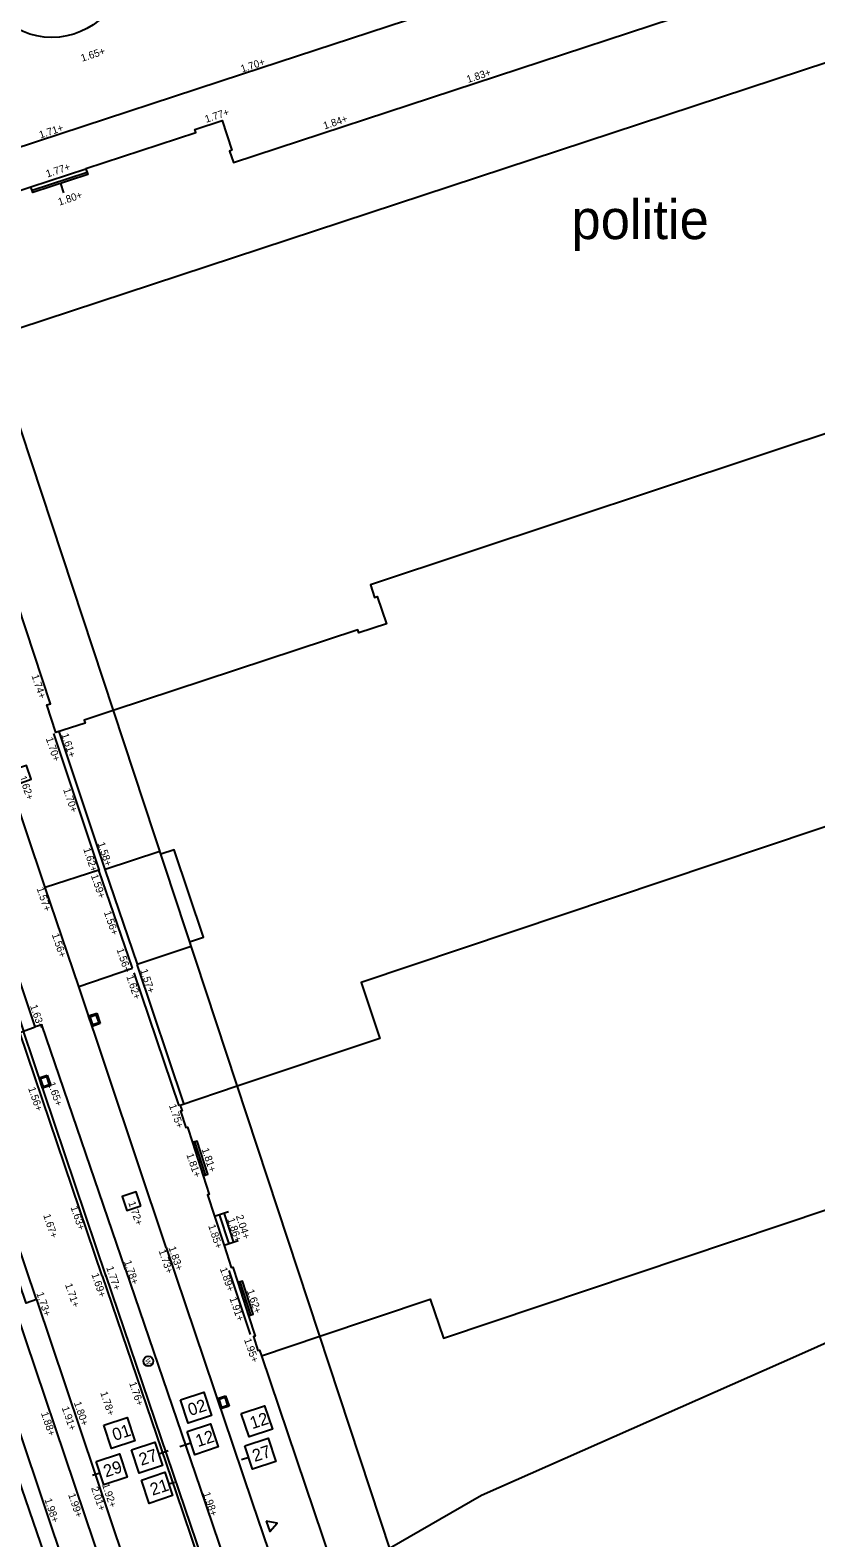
# Model space of a CAD drawing. Extents: x 122462 to 123306, y 485548 to 486417.
# Drawn here: x 122832.1 to 122864.1, y 486111.7 to 486173.1 of the extents above; entities that cross this region are included whole.
import ezdxf

# ---------------------------------------------------------------- set-up
doc = ezdxf.new("R2010")
doc.units = 0
for name, color, linetype in [('B nummers', 7, 'Continuous'), ('B-WE-AL-WERKGRENS-G', 7, 'Continuous'), ('B-WE-GR-BOOM-S', 7, 'Continuous'), ('B-WE-IE-MEUBILAIR_WEGMEUBILAIR-S', 7, 'Continuous'), ('B-WE-IE-TERREINAFSCHEIDING_KUNSTMATIG_HEKWERK-G', 7, 'Continuous'), ('B-WE-OG-BEBOUWING_RAAM-G', 7, 'Continuous'), ('B-WE-OG-BEBOUWING_TRAP-G', 7, 'Continuous'), ('B-WE-OG-HOOGTEPUNT-S', 7, 'Continuous'), ('B-WE-OG-TOPOGRAFIE_GEVELDETAIL-G', 7, 'Continuous'), ('B-WE-OG-TOPOGRAFIE_MUUR-G', 7, 'Continuous'), ('B-WE-OG-TOPOKAART-G', 7, 'Continuous'), ('B-WE-VH-KANTOPSLUITING_OPSLUITBAND_100X200-G', 7, 'Continuous'), ('B-WE-VH-MATERIAALGRENS-G', 7, 'Continuous'), ('B-WE-VW-MARKERING_LANGS_STREEP_DOORGETROKKEN_010-G', 7, 'Continuous'), ('Level 1', 7, 'Continuous'), ('Level 16', 7, 'Continuous'), ('Level 17', 7, 'Continuous'), ('Level 62', 7, 'Continuous'), ('V Inritband 100x50', 7, 'Continuous'), ('V materiaalscheiding algemeen', 7, 'Continuous'), ('V meubilair trammast', 7, 'Continuous'), ('V Rails', 7, 'Continuous'), ('V riool putdeksel', 7, 'Continuous'), ('V riool trottoirkolk', 7, 'Continuous'), ('V RWS-band 115-225x250 mm specie', 7, 'Continuous'), ('V trottoirband 180-200x250 mm specie', 7, 'Continuous')]:
    doc.layers.add(name, color=color, linetype=linetype)

msp = doc.modelspace()

# ---------------------------------------------------------------- linework, layer by layer
at = {"layer": 'B nummers'}
for p, q in [((122837.339, 486115.174), (122837.732, 486115.304)), ((122838.65, 486115.607), (122838.202, 486115.459)), ((122841.002, 486115.014), (122840.712, 486114.918)), ((122834.948, 486114.385), (122834.645, 486114.286)), ((122837.746, 486113.94), (122837.984, 486114.018))]:
    msp.add_line(p, q, dxfattribs=at)
for points in [[(122838.226, 486117.362), (122839.176, 486117.676), (122839.489, 486116.726), (122838.539, 486116.413)], [(122840.701, 486116.81), (122841.651, 486117.124), (122841.964, 486116.174), (122841.015, 486115.861)], [(122835.102, 486116.332), (122836.052, 486116.645), (122836.365, 486115.695), (122835.415, 486115.382)], [(122838.494, 486116.082), (122839.443, 486116.395), (122839.757, 486115.446), (122838.807, 486115.132)], [(122836.232, 486115.336), (122837.182, 486115.649), (122837.495, 486114.699), (122836.546, 486114.386)], [(122840.846, 486115.489), (122841.795, 486115.802), (122842.109, 486114.853), (122841.159, 486114.539)], [(122834.791, 486114.86), (122835.741, 486115.174), (122836.054, 486114.224), (122835.105, 486113.911)], [(122836.64, 486114.101), (122837.589, 486114.415), (122837.903, 486113.465), (122836.953, 486113.152)]]:
    msp.add_lwpolyline(points, close=True, dxfattribs=at)
at = {"layer": 'B-WE-AL-WERKGRENS-G'}
msp.add_lwpolyline([(122857.632, 486078.279), (122830.484, 486160.606), (122900.937, 486183.81), (122887.855, 486222.555), (122665.445, 486149.273), (122678.196, 486110.449), (122807.072, 486152.895), (122835.324, 486068.154)], dxfattribs=at)
at = {"layer": 'B-WE-GR-BOOM-S'}
msp.add_circle((122832.992, 486175.817), 3, dxfattribs=at)
at = {"layer": 'B-WE-IE-MEUBILAIR_WEGMEUBILAIR-S'}
msp.add_circle((122836.917, 486118.938), 0.2, dxfattribs=at)
at = {"layer": 'B-WE-IE-TERREINAFSCHEIDING_KUNSTMATIG_HEKWERK-G'}
for points in [[(122837.383, 486139.685), (122835.162, 486138.946), (122833.293, 486144.564)], [(122838.657, 486135.821), (122836.47, 486135.09)], [(122838.376, 486129.388), (122836.47, 486135.09)]]:
    msp.add_lwpolyline(points, dxfattribs=at)
at = {"layer": 'B-WE-OG-BEBOUWING_RAAM-G'}
for points in [[(122838.71, 486127.837), (122839.147, 486126.487), (122839.338, 486126.549), (122838.901, 486127.898)], [(122840.555, 486122.138), (122840.992, 486120.788), (122841.182, 486120.85), (122840.745, 486122.199)]]:
    msp.add_lwpolyline(points, close=True, dxfattribs=at)
for points in [[(122839.242, 486126.518), (122838.805, 486127.868)], [(122841.087, 486120.819), (122840.65, 486122.169)]]:
    msp.add_lwpolyline(points, dxfattribs=at)
at = {"layer": 'B-WE-OG-BEBOUWING_TRAP-G'}
for p, q in [((122839.61, 486124.846), (122839.998, 486123.648)), ((122839.8, 486124.908), (122840.188, 486123.71)), ((122839.99, 486124.97), (122840.378, 486123.771))]:
    msp.add_line(p, q, dxfattribs=at)
at = {"layer": 'B-WE-OG-TOPOGRAFIE_GEVELDETAIL-G'}
for p, q in [((122832.19, 486166.597), (122834.429, 486167.331)), ((122833.341, 486166.869), (122833.465, 486166.489))]:
    msp.add_line(p, q, dxfattribs=at)
msp.add_lwpolyline([(122832.144, 486166.739), (122834.382, 486167.474), (122834.46, 486167.236), (122832.222, 486166.501)], close=True, dxfattribs=at)
at = {"layer": 'B-WE-OG-TOPOGRAFIE_MUUR-G'}
msp.add_line((122841.519, 486119.16), (122844.35, 486110.759), dxfattribs=at)
at = {"layer": 'B-WE-OG-TOPOKAART-G'}
for points in [[(122834.381, 486167.476), (122838.846, 486168.947), (122838.807, 486169.064), (122839.92, 486169.429), (122840.318, 486168.223), (122840.226, 486168.193), (122840.381, 486167.723), (122860.049, 486174.179)], [(122835.493, 486145.416), (122834.311, 486145.025), (122834.351, 486144.904), (122833.159, 486144.52), (122832.786, 486145.648), (122832.936, 486145.697), (122826.954, 486163.84), (122826.803, 486163.791), (122826.41, 486164.979), (122827.587, 486165.368), (122827.626, 486165.251), (122832.144, 486166.739)], [(122840.535, 486130.128), (122838.219, 486129.35), (122838.292, 486129.132), (122838.229, 486129.11), (122838.446, 486128.445), (122838.507, 486128.465), (122838.71, 486127.837)], [(122839.147, 486126.487), (122839.393, 486125.728), (122839.331, 486125.708), (122839.61, 486124.846), (122840.181, 486125.031)], [(122840.569, 486123.833), (122839.998, 486123.648), (122840.29, 486122.746), (122840.352, 486122.766), (122840.555, 486122.138)], [(122840.992, 486120.788), (122841.26, 486119.959), (122841.198, 486119.939), (122841.38, 486119.37), (122841.443, 486119.391), (122841.519, 486119.16), (122843.889, 486119.956)]]:
    msp.add_lwpolyline(points, dxfattribs=at)
at = {"layer": 'B-WE-VH-KANTOPSLUITING_OPSLUITBAND_100X200-G'}
for points in [[(122834.927, 486138.912), (122833.07, 486144.482)], [(122838.167, 486129.333), (122836.336, 486134.745)], [(122841.076, 486120.024), (122840.202, 486122.634)]]:
    msp.add_lwpolyline(points, dxfattribs=at)
at = {"layer": 'B-WE-VH-MATERIAALGRENS-G'}
for points in [[(122826.354, 486164.961), (122825.848, 486166.443), (122832.41, 486168.591), (122840.754, 486171.332), (122848.12, 486173.75), (122858.853, 486177.307), (122858.545, 486178.241), (122874.617, 486183.538), (122874.928, 486182.584), (122877.008, 486183.297), (122898.435, 486190.341)], [(122836.271, 486134.939), (122834.911, 486138.929)], [(122836.476, 486135.092), (122835.162, 486138.946)]]:
    msp.add_lwpolyline(points, dxfattribs=at)
at = {"layer": 'B-WE-VW-MARKERING_LANGS_STREEP_DOORGETROKKEN_010-G'}
msp.add_lwpolyline([(122842.379, 486082.508), (122834.669, 486105.323), (122830.244, 486118.192), (122825.281, 486132.973), (122822.384, 486141.602), (122818.71, 486152.508)], dxfattribs=at)
at = {"layer": 'Level 1'}
for points in [[(122909.585, 486143.395), (122901.057, 486168.787), (122881.468, 486162.304), (122881.638, 486161.79), (122881.732, 486161.821), (122882.121, 486160.646), (122880.986, 486160.273), (122880.955, 486160.368), (122867.199, 486155.844), (122867.231, 486155.749), (122866.093, 486155.375), (122865.709, 486156.53), (122865.804, 486156.562), (122865.635, 486157.072), (122845.954, 486150.537), (122846.124, 486150.024), (122846.234, 486150.06), (122846.601, 486148.954), (122845.482, 486148.584), (122845.442, 486148.705), (122835.493, 486145.416)], [(122899.919, 486149.707), (122899.047, 486152.304), (122845.573, 486134.345), (122846.335, 486132.076), (122840.535, 486130.128)], [(122843.889, 486119.956), (122848.39, 486121.468), (122848.927, 486119.869), (122903.756, 486138.283), (122903.184, 486139.984)]]:
    msp.add_lwpolyline(points, dxfattribs=at)
at = {"layer": 'Level 16'}
msp.add_lwpolyline([(122846.733, 486111.33), (122850.475, 486113.488), (122863.386, 486119.194), (122871.86, 486122.983), (122876.67, 486124.799)], dxfattribs=at)
at = {"layer": 'Level 17'}
msp.add_lwpolyline([(122838.595, 486136.01), (122839.16, 486136.199), (122837.973, 486139.753), (122837.421, 486139.569)], dxfattribs=at)
at = {"layer": 'V Inritband 100x50'}
for points in [[(122832.367, 486121.446), (122831.947, 486121.305), (122828.09, 486132.668), (122825.079, 486141.609), (122824.762, 486142.578), (122825.19, 486142.715)], [(122832.367, 486121.446), (122828.514, 486132.846), (122825.512, 486141.812), (122825.19, 486142.715)], [(122831.838, 486132.366), (122832.314, 486132.542), (122829.781, 486140.105), (122829.312, 486139.948), (122831.838, 486132.366)]]:
    msp.add_lwpolyline(points, dxfattribs=at)
at = {"layer": 'V materiaalscheiding algemeen'}
for points in [[(122834.088, 486134.186), (122832.725, 486138.213)], [(122835.041, 486122.41), (122831.696, 486132.317), (122831.838, 486132.366)], [(122835.992, 486122.672), (122832.591, 486132.63), (122832.314, 486132.542)], [(122835.041, 486122.41), (122838.047, 486113.577), (122840.172, 486107.322), (122840.315, 486107.372)], [(122835.992, 486122.672), (122839.022, 486113.767)]]:
    msp.add_lwpolyline(points, dxfattribs=at)
at = {"layer": 'V meubilair trammast'}
msp.add_lwpolyline([(122841.718, 486112.431), (122841.863, 486112.005), (122842.159, 486112.343)], close=True, dxfattribs=at)
at = {"layer": 'V Rails'}
for p, q in [((122818.309, 486155.586), (122834.974, 486106.268)), ((122819.673, 486156.047), (122836.339, 486106.728))]:
    msp.add_line(p, q, dxfattribs=at)
at = {"layer": 'V riool putdeksel'}
for points in [[(122831.39, 486142.988), (122831.59, 486142.422), (122832.156, 486142.622), (122831.956, 486143.188)], [(122836.618, 486125.262), (122836.428, 486125.832), (122835.858, 486125.642), (122836.048, 486125.072)]]:
    msp.add_lwpolyline(points, close=True, dxfattribs=at)
at = {"layer": 'V riool trottoirkolk'}
for p, q in [((122834.488, 486132.992), (122834.82, 486133.103)), ((122834.631, 486132.565), (122834.488, 486132.992)), ((122834.504, 486132.944), (122834.509, 486132.946)), ((122834.547, 486132.864), (122834.521, 486132.939)), ((122834.536, 486132.849), (122834.54, 486132.851)), ((122834.544, 486132.826), (122834.548, 486132.827)), ((122834.586, 486132.745), (122834.561, 486132.821)), ((122834.82, 486133.103), (122834.963, 486132.676)), ((122834.575, 486132.731), (122834.58, 486132.732)), ((122834.583, 486132.707), (122834.588, 486132.709)), ((122834.611, 486132.671), (122834.601, 486132.702)), ((122834.626, 486132.626), (122834.611, 486132.671)), ((122834.615, 486132.612), (122834.62, 486132.614)), ((122834.963, 486132.676), (122834.631, 486132.565)), ((122832.475, 486130.474), (122832.807, 486130.586)), ((122832.619, 486130.048), (122832.475, 486130.474)), ((122832.491, 486130.427), (122832.496, 486130.428)), ((122832.534, 486130.346), (122832.508, 486130.422)), ((122832.807, 486130.586), (122832.95, 486130.159)), ((122832.523, 486130.332), (122832.528, 486130.334)), ((122832.531, 486130.308), (122832.536, 486130.31)), ((122832.574, 486130.228), (122832.548, 486130.304)), ((122832.563, 486130.214), (122832.568, 486130.215)), ((122832.571, 486130.19), (122832.576, 486130.191)), ((122832.599, 486130.154), (122832.588, 486130.185)), ((122832.614, 486130.109), (122832.599, 486130.154)), ((122832.603, 486130.095), (122832.607, 486130.097)), ((122832.95, 486130.159), (122832.619, 486130.048)), ((122839.73, 486117.422), (122840.062, 486117.534)), ((122840.062, 486117.534), (122840.206, 486117.107)), ((122839.874, 486116.995), (122839.73, 486117.422)), ((122839.746, 486117.374), (122839.751, 486117.376)), ((122839.789, 486117.294), (122839.764, 486117.37)), ((122839.778, 486117.28), (122839.783, 486117.281)), ((122839.786, 486117.256), (122839.791, 486117.258)), ((122839.829, 486117.176), (122839.804, 486117.251)), ((122839.818, 486117.161), (122839.823, 486117.163)), ((122839.826, 486117.138), (122839.831, 486117.139)), ((122839.854, 486117.102), (122839.843, 486117.133)), ((122839.869, 486117.057), (122839.854, 486117.102)), ((122839.858, 486117.043), (122839.863, 486117.044)), ((122840.206, 486117.107), (122839.874, 486116.995))]:
    msp.add_line(p, q, dxfattribs=at)
for points in [[(122834.788, 486133.039), (122834.9, 486132.707), (122834.663, 486132.628), (122834.551, 486132.96)], [(122832.775, 486130.522), (122832.887, 486130.191), (122832.65, 486130.111), (122832.538, 486130.443)], [(122840.031, 486117.47), (122840.142, 486117.139), (122839.905, 486117.059), (122839.794, 486117.39)]]:
    msp.add_lwpolyline(points, close=True, dxfattribs=at)
for centre, start, end in [((122834.512, 486132.936), 18.5109, 108.5109), ((122834.537, 486132.86), 288.5109, 18.5109), ((122834.552, 486132.818), 18.5109, 108.5109), ((122834.577, 486132.742), 288.5109, 18.5109), ((122834.591, 486132.699), 18.5109, 108.5109), ((122834.617, 486132.623), 288.5109, 18.5109), ((122832.499, 486130.419), 18.607, 108.607), ((122832.525, 486130.343), 288.607, 18.607), ((122832.539, 486130.3), 18.607, 108.607), ((122832.564, 486130.225), 288.607, 18.607), ((122832.579, 486130.182), 18.607, 108.607), ((122832.604, 486130.106), 288.607, 18.607), ((122839.754, 486117.367), 18.6186, 108.6186), ((122839.78, 486117.291), 288.6186, 18.6186), ((122839.794, 486117.248), 18.6186, 108.6186), ((122839.82, 486117.172), 288.6186, 18.6186), ((122839.834, 486117.13), 18.6186, 108.6186), ((122839.86, 486117.054), 288.6186, 18.6186)]:
    msp.add_arc(centre, 0.01, start, end, dxfattribs=at)
at = {"layer": 'V RWS-band 115-225x250 mm specie'}
msp.add_lwpolyline([(122832.367, 486121.446), (122837.147, 486107.234)], dxfattribs=at)
at = {"layer": 'V trottoirband 180-200x250 mm specie'}
for points in [[(122834.911, 486138.929), (122832.725, 486138.213), (122824.045, 486164.077)], [(122837.646, 486123.559), (122834.088, 486134.186), (122836.271, 486134.939)], [(122835.198, 486122.386), (122831.838, 486132.366)], [(122851.83, 486081.654), (122846.225, 486098.276), (122841.156, 486113.188), (122837.659, 486123.568)], [(122844.724, 486094.463), (122841.797, 486103.007), (122838.189, 486113.625), (122835.183, 486122.458)], [(122839.022, 486113.767), (122842.561, 486103.334), (122845.536, 486094.754)]]:
    msp.add_lwpolyline(points, dxfattribs=at)

# ---------------------------------------------------------------- texts
at = {"layer": 'B nummers'}
for s, p in [('02', (122838.624, 486116.704)), ('01', (122835.548, 486115.689)), ('12', (122841.147, 486116.168)), ('12', (122838.939, 486115.439)), ('27', (122836.631, 486114.677)), ('27', (122841.244, 486114.831)), ('29', (122835.19, 486114.202)), ('21', (122837.085, 486113.458))]:
    msp.add_text(s, height=0.5, rotation=18.26033, dxfattribs=at).set_placement(p)
at = {"layer": 'B-WE-IE-MEUBILAIR_WEGMEUBILAIR-S'}
msp.add_text('W', height=0.2, rotation=288.4511, dxfattribs=at).set_placement((122836.783, 486119.006))
at = {"layer": 'B-WE-OG-HOOGTEPUNT-S'}
for s, rotation, p in [('1.65+', 18.3542, (122834.228, 486171.823)), ('1.70+', 18.3542, (122840.731, 486171.383)), ('1.83+', 18.3542, (122849.924, 486170.957)), ('1.77+', 18.3542, (122839.274, 486169.338)), ('1.71+', 18.3542, (122832.53, 486168.698)), ('1.84+', 18.3542, (122844.091, 486169.068)), ('1.77+', 18.3542, (122832.81, 486167.112)), ('1.80+', 18.3542, (122833.3, 486165.966)), ('1.74+', 288.5518, (122832.16, 486146.837)), ('1.61+', 288.5518, (122833.374, 486144.443)), ('1.70+', 288.5518, (122832.742, 486144.28)), ('1.62+', 288.5518, (122831.661, 486142.712)), ('1.70+', 288.5518, (122833.45, 486142.206)), ('1.62+', 288.5518, (122834.267, 486139.78)), ('1.58+', 288.5518, (122834.851, 486140.015)), ('1.59+', 288.8218, (122834.577, 486138.703)), ('1.57+', 288.5518, (122832.369, 486138.178)), ('1.56+', 288.8218, (122835.108, 486137.208)), ('1.56+', 288.5518, (122832.987, 486136.3)), ('1.56+', 288.5518, (122835.621, 486135.692)), ('1.57+', 288.5518, (122836.588, 486134.851)), ('1.62+', 288.5518, (122836.019, 486134.596)), ('1.63+', 288.8218, (122832.103, 486133.399)), ('1.56+', 288.8218, (122832.026, 486130.045)), ('1.65+', 288.8218, (122832.83, 486130.249)), ('1.75+', 288.8882, (122837.752, 486129.347)), ('1.81+', 288.8882, (122838.46, 486127.345)), ('1.81+', 288.8882, (122839.082, 486127.561)), ('1.67+', 288.5604, (122832.638, 486124.88)), ('1.63+', 288.5604, (122833.753, 486125.202)), ('1.72+', 288.8218, (122836.097, 486125.392)), ('2.04+', 287.9403, (122840.476, 486124.845)), ('1.85+', 287.9403, (122839.351, 486124.454)), ('1.86+', 287.9403, (122840.131, 486124.718)), ('1.78+', 288.8218, (122835.928, 486122.993)), ('1.73+', 288.8882, (122837.333, 486123.431)), ('1.83+', 288.8882, (122837.735, 486123.557)), ('1.69+', 288.8218, (122834.6, 486122.47)), ('1.77+', 288.8218, (122835.201, 486122.751)), ('1.89+', 288.8882, (122839.822, 486122.702)), ('1.71+', 288.8218, (122833.526, 486122.055)), ('1.62+', 288.8882, (122840.92, 486121.807)), ('1.73+', 288.8218, (122832.36, 486121.699)), ('1.91+', 288.8882, (122840.217, 486121.492)), ('1.95+', 288.8882, (122840.808, 486119.815)), ('1.76+', 288.6561, (122836.133, 486118.049)), ('1.78+', 288.6561, (122834.959, 486117.653)), ('1.88+', 288.6561, (122832.546, 486116.824)), ('1.91+', 288.6561, (122833.391, 486117.046)), ('1.80+', 288.6561, (122833.887, 486117.244)), ('2.01+', 288.6561, (122834.588, 486113.779)), ('1.92+', 288.6561, (122835.03, 486113.91)), ('1.98+', 288.6561, (122832.69, 486113.304)), ('1.99+', 288.6561, (122833.653, 486113.506)), ('1.98+', 288.7376, (122839.136, 486113.563))]:
    msp.add_text(s, height=0.3, rotation=rotation, dxfattribs=at).set_placement(p)
at = {"layer": 'Level 62'}
msp.add_text('politie', height=1.6, dxfattribs=at).set_placement((122854.132, 486164.606))

doc.saveas('drawing.dxf')
